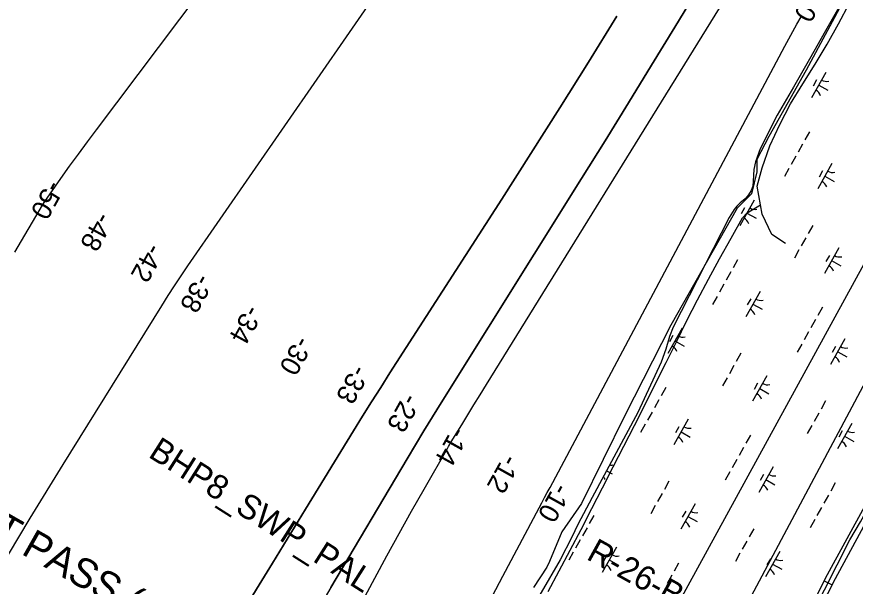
# Model space of a CAD drawing. Extents: x 3913936 to 3933962, y 195330 to 217741.
# Drawn here: x 3927100 to 3928535, y 208120 to 209094 of the extents above; entities that cross this region are included whole.
import ezdxf

# ---------------------------------------------------------------- set-up
doc = ezdxf.new("R2010")
doc.units = 0
for name, color, linetype in [('V-CHAN-NAID', 7, 'Continuous'), ('V-RIVR-EDGE', 7, 'Continuous'), ('V-RIVR-GAGE-IDEN', 7, 'Continuous'), ('V-RIVR-RANG', 7, 'Continuous'), ('V-RIVR-RANG-IDEN', 7, 'Continuous'), ('V-ROAD-CNTR', 7, 'Continuous'), ('V-RRAP-FSHR', 7, 'Continuous'), ('V-TOPO-DPTH', 7, 'Continuous'), ('V-TOPO-MAJR', 7, 'Continuous'), ('V-TOPO-MINR', 7, 'Continuous'), ('V-UTIL-LINE', 7, 'Continuous'), ('V-WETL-SWMP', 7, 'Continuous')]:
    doc.layers.add(name, color=color, linetype=linetype)

msp = doc.modelspace()

# ---------------------------------------------------------------- linework, layer by layer
at = {"layer": 'V-RIVR-EDGE'}
msp.add_lwpolyline([(3928556.5, 209199.4), (3928450.9, 209002.8), (3928386.8, 208889.3), (3928366.6, 208850), (3928366.6, 208828.7), (3928357.6, 208791.6), (3928332.9, 208766.9), (3928219.4, 208566.9), (3928140.8, 208411.9), (3928066.7, 208261.4), (3928033, 208213.1), (3928011.6, 208162.5), (3928007.1, 208152.4), (3927984.7, 208117.6)], dxfattribs=at)
at = {"layer": 'V-ROAD-CNTR'}
msp.add_line((3928482, 208129.1), (3928495.4, 208122.3), dxfattribs=at)
for points in [[(3928044.2, 207343.6), (3928094.5, 207444.5), (3928133.3, 207517.5), (3928180.5, 207605.3), (3928235.4, 207695.3), (3928288.8, 207774.9), (3928328.2, 207845), (3928371.8, 207915), (3928403.4, 207978.7), (3928448.6, 208063), (3928487.6, 208140.1), (3928551.3, 208257.1), (3928589.1, 208328.3), (3928660.5, 208463), (3928682.4, 208493.9)], [(3928387.7, 207913.2), (3928416.7, 207971.8), (3928461.9, 208056.1), (3928500.9, 208133.1), (3928564.5, 208250)], [(3927948.7, 207158.5), (3927983, 207221.8), (3928027.3, 207302.1), (3928070.8, 207383.9), (3928132.7, 207501), (3928178.9, 207584.5), (3928208, 207638.7), (3928249, 207705.3), (3928302.8, 207784.1), (3928343.9, 207858.3), (3928395.8, 207942.8), (3928525.9, 208199.6)]]:
    msp.add_lwpolyline(points, dxfattribs=at)
msp.add_spline([(3928525.9, 208199.6), (3928663.5, 208448.7), (3928729.3, 208575.7), (3928772.5, 208644.8), (3928793, 208671.2), (3928813.2, 208686), (3928850, 208702.1), (3928901.4, 208723.3), (3928941.2, 208746.5), (3928980.6, 208763.6), (3929011.7, 208780.2), (3929053.1, 208788.8), (3929116.6, 208799.7), (3929152.6, 208808.4), (3929198.1, 208822), (3929228.3, 208840.3), (3929280.5, 208872.7), (3929342.1, 208906.6), (3929394.3, 208930.8), (3929439, 208947.7), (3929467.8, 208956.8), (3929496.7, 208976.4), (3929523.6, 209009.7), (3929552.1, 209061.3), (3929562.8, 209097.6), (3929549.9, 209122.5), (3929531.6, 209153.6), (3929490.5, 209225.5), (3929461.6, 209289.1), (3929459.6, 209329.4)], degree=3, dxfattribs=at)
at = {"layer": 'V-RRAP-FSHR'}
for points in [[(3928415.6, 208706.5), (3928392, 208721.8), (3928375.9, 208756.5), (3928367.3, 208804.2), (3928375.7, 208835.6), (3928388.7, 208873.3), (3928405.6, 208909.9), (3928423.9, 208945.1), (3928445.1, 208979.4), (3928466.4, 209012.9), (3928486.9, 209047.2), (3928506.2, 209082.3), (3928525.1, 209117.5)], [(3928009.7, 208111.3), (3928028.5, 208146.6), (3928047.2, 208182), (3928065.9, 208217.3), (3928084.2, 208252.9), (3928102.4, 208288.5), (3928120.6, 208324.1), (3928139, 208359.7), (3928157.3, 208395.2), (3928175.5, 208430.8), (3928193.3, 208466.7), (3928211.6, 208502.5), (3928228.9, 208538.3), (3928246.8, 208574.8), (3928264.8, 208609.8), (3928283.8, 208645.2), (3928302.9, 208680.2), (3928322.6, 208715.3), (3928341.9, 208750), (3928350.1, 208758.8), (3928373, 208772.3)]]:
    msp.add_lwpolyline(points, dxfattribs=at)
at = {"layer": 'V-TOPO-DPTH'}
for points in [[(3927068.2, 208144.7), (3927123.5, 208236.7), (3927179.7, 208328.3), (3927348.6, 208600), (3927359.4, 208617.2), (3927370.5, 208634.2), (3927381.8, 208651.2), (3927393.2, 208668), (3927780.5, 209227.3), (3927802.6, 209259), (3927824.8, 209290.6), (3927847.3, 209322), (3927869.9, 209353.4), (3927910.8, 209409.7), (3927913.1, 209412.8), (3927915.4, 209415.9), (3927917.8, 209419), (3927920.1, 209422.1), (3927962.4, 209477), (3928558.3, 210083.6), (3928575.6, 210105.9), (3928593, 210128), (3928610.7, 210149.9), (3928628.4, 210171.7)], [(3927068.2, 208144.7), (3927123.5, 208236.7), (3927179.7, 208328.3), (3927348.6, 208600), (3927359.4, 208617.2), (3927370.5, 208634.2), (3927381.8, 208651.2), (3927393.2, 208668), (3927780.5, 209227.3), (3927802.6, 209259), (3927824.8, 209290.6), (3927847.3, 209322), (3927869.9, 209353.4), (3927910.8, 209409.7), (3927913.1, 209412.8), (3927915.4, 209415.9), (3927917.8, 209419), (3927920.1, 209422.1), (3927962.4, 209477), (3927986.8, 209501.8)], [(3928264.6, 209139.6), (3928226.2, 209076.5), (3928186.6, 209011.6), (3928146.8, 208946.8), (3928106.8, 208882.2), (3928066.6, 208817.7), (3927826.4, 208433.6), (3927811.7, 208409.7), (3927797, 208385.9), (3927782.5, 208361.9), (3927768.2, 208337.8), (3927637.8, 208117.9), (3927579.5, 208018.9), (3927521.6, 207919.6), (3927464.3, 207820.1), (3927407.3, 207720.3), (3927308, 207545.4), (3927301, 207532.9), (3927294, 207520.4), (3927287, 207507.8), (3927280.1, 207495.3), (3927231.5, 207406.3)], [(3928264.6, 209139.6), (3928226.2, 209076.5), (3928186.6, 209011.6), (3928146.8, 208946.8), (3928106.8, 208882.2), (3928066.6, 208817.7), (3927826.4, 208433.6), (3927811.7, 208409.7), (3927797, 208385.9), (3927782.5, 208361.9), (3927768.2, 208337.8), (3927637.8, 208117.9)], [(3927038.6, 207382.4), (3927156.9, 207550), (3927168.8, 207567.2), (3927180.5, 207584.4), (3927191.8, 207601.9), (3927203, 207619.5), (3927367.6, 207884.4), (3927424.5, 207976.1), (3927481.2, 208067.8), (3927537.8, 208159.7), (3927594.3, 208251.7), (3927676.5, 208385.8), (3927691.9, 208410.7), (3927707.4, 208435.5), (3927723, 208460.2), (3927738.8, 208484.9), (3927930.3, 208782.3), (3927980.1, 208860.2), (3928029.6, 208938.3), (3928078.6, 209016.7), (3928127.2, 209095.3)], [(3928127.2, 209095.3), (3928078.6, 209016.7), (3928029.6, 208938.3), (3927980.1, 208860.2), (3927930.3, 208782.3), (3927738.8, 208484.9), (3927723, 208460.2), (3927707.4, 208435.5), (3927691.9, 208410.7), (3927676.5, 208385.8), (3927594.3, 208251.7), (3927537.8, 208159.7), (3927481.2, 208067.8), (3927424.5, 207976.1), (3927367.6, 207884.4), (3927203, 207619.5), (3927191.8, 207601.9), (3927180.5, 207584.4), (3927168.8, 207567.2), (3927156.9, 207550), (3927038.6, 207382.4)], [(3927231.5, 207406.3), (3927520, 207339.4), (3927529.9, 207360.6), (3927539.9, 207381.8), (3927550.3, 207402.8), (3927560.9, 207423.6), (3927790.8, 207867.9), (3927825.8, 207935.4), (3927861, 208002.8), (3927896.4, 208070.1), (3927932, 208137.3), (3927994, 208254.1), (3927998.7, 208262.8), (3928003.3, 208271.6), (3928008, 208280.4), (3928012.7, 208289.1), (3928414.4, 209043.8), (3928421.2, 209056.5), (3928428.2, 209069.2), (3928435.2, 209081.8), (3928442.3, 209094.4)]]:
    msp.add_lwpolyline(points, dxfattribs=at)
at = {"layer": 'V-TOPO-MAJR'}
msp.add_lwpolyline([(3927097, 208691.7), (3927144.5, 208772.2), (3927145.4, 208773.7), (3927147.3, 208776.6), (3927148.3, 208778.1), (3927175.9, 208817.4), (3927190.9, 208838.4), (3927205.9, 208859.3), (3927221.2, 208880.1), (3927236.6, 208900.7), (3927699.3, 209515.6), (3927711.7, 209532), (3927724.1, 209548.5), (3927736.5, 209564.9), (3927749, 209581.3), (3928265.5, 210260.9)], dxfattribs=at)
at = {"layer": 'V-TOPO-MINR'}
for points in [[(3927068.2, 208144.7), (3927123.5, 208236.7), (3927179.7, 208328.3), (3927348.6, 208600), (3927359.4, 208617.2), (3927370.5, 208634.2), (3927381.8, 208651.2), (3927393.2, 208668), (3927780.5, 209227.3), (3927802.6, 209259), (3927824.8, 209290.6), (3927847.3, 209322), (3927869.9, 209353.4), (3927910.8, 209409.7), (3927913.1, 209412.8), (3927915.4, 209415.9), (3927917.8, 209419), (3927920.1, 209422.1), (3927962.4, 209477), (3928558.3, 210083.6), (3928575.6, 210105.9), (3928593, 210128), (3928610.7, 210149.9), (3928628.4, 210171.7)], [(3927386.2, 207525.1), (3927713, 208134), (3927733.7, 208172.2), (3927754.7, 208210.4), (3927775.9, 208248.3), (3927797.4, 208286.2), (3927837.7, 208356.6), (3927839.2, 208359.2), (3927840.6, 208361.7), (3927842.1, 208364.2), (3927843.7, 208366.8), (3927861.6, 208396.2), (3927872.1, 208413.4), (3927882.6, 208430.6), (3927893.2, 208447.7), (3927903.8, 208464.9), (3928332.2, 209157.2)], [(3927637.8, 208117.9), (3927768.2, 208337.8), (3927782.5, 208361.9), (3927797, 208385.9), (3927811.7, 208409.7), (3927826.4, 208433.6), (3928066.6, 208817.7), (3928106.8, 208882.2), (3928146.8, 208946.8), (3928186.6, 209011.6), (3928226.2, 209076.5), (3928264.6, 209139.6)], [(3927038.6, 207382.4), (3927156.9, 207550), (3927168.8, 207567.2), (3927180.5, 207584.4), (3927191.8, 207601.9), (3927203, 207619.5), (3927367.6, 207884.4), (3927424.5, 207976.1), (3927481.2, 208067.8), (3927537.8, 208159.7), (3927594.3, 208251.7), (3927676.5, 208385.8), (3927691.9, 208410.7), (3927707.4, 208435.5), (3927723, 208460.2), (3927738.8, 208484.9), (3927930.3, 208782.3), (3927980.1, 208860.2), (3928029.6, 208938.3), (3928078.6, 209016.7), (3928127.2, 209095.3)], [(3927520, 207339.4), (3927529.9, 207360.6), (3927539.9, 207381.8), (3927550.3, 207402.8), (3927560.9, 207423.6), (3927790.8, 207867.9), (3927825.8, 207935.4), (3927861, 208002.8), (3927896.4, 208070.1), (3927932, 208137.3), (3927994, 208254.1), (3927998.7, 208262.8), (3928003.3, 208271.6), (3928008, 208280.4), (3928012.7, 208289.1), (3928414.4, 209043.8), (3928421.2, 209056.5), (3928428.2, 209069.2), (3928435.2, 209081.8), (3928442.3, 209094.4)]]:
    msp.add_lwpolyline(points, dxfattribs=at)
at = {"layer": 'V-UTIL-LINE'}
for points in [[(3928017.7, 207698.3), (3929347.6, 210129), (3930421.7, 211210.3)], [(3930525.7, 211151.4), (3928710.9, 208768), (3928100.1, 207621.2)]]:
    msp.add_lwpolyline(points, dxfattribs=at)
at = {"layer": 'V-WETL-SWMP'}
for p, q in [((3928484.7, 208999), (3928460.2, 208955.4)), ((3928468.7, 208986.2), (3928462.8, 208975.8)), ((3928472.5, 208977.2), (3928488.2, 208968.4)), ((3928456.7, 208897.4), (3928448.9, 208883.5)), ((3928444.9, 208876.5), (3928437.1, 208862.6)), ((3928433.2, 208855.6), (3928425.3, 208841.6)), ((3928495.1, 208843.2), (3928470.6, 208799.6)), ((3928421.4, 208834.7), (3928413.6, 208820.7)), ((3928479.1, 208830.5), (3928473.2, 208820)), ((3928482.9, 208821.4), (3928498.6, 208812.6)), ((3928361.7, 208780.3), (3928337.2, 208736.7)), ((3928345.7, 208767.5), (3928339.8, 208757)), ((3928349.5, 208758.5), (3928365.2, 208749.7)), ((3928462.2, 208737.2), (3928454.3, 208723.3)), ((3928450.4, 208716.3), (3928442.6, 208702.4)), ((3928438.6, 208695.4), (3928430.8, 208681.5)), ((3928506.7, 208698.8), (3928482.2, 208655.2)), ((3928490.7, 208686), (3928484.8, 208675.5)), ((3928333.7, 208678.7), (3928325.9, 208664.7)), ((3928494.5, 208677), (3928510.2, 208668.2)), ((3928322, 208657.7), (3928314.1, 208643.8)), ((3928310.2, 208636.8), (3928302.4, 208622.9)), ((3928372.1, 208624.5), (3928347.6, 208580.9)), ((3928298.5, 208615.9), (3928290.6, 208602)), ((3928356.1, 208611.7), (3928350.2, 208601.2)), ((3928359.9, 208602.7), (3928375.6, 208593.9)), ((3928478.7, 208597.2), (3928470.9, 208583.2)), ((3928467, 208576.2), (3928459.1, 208562.3)), ((3928238.8, 208561.5), (3928214.3, 208517.9)), ((3928455.2, 208555.3), (3928447.4, 208541.4)), ((3928222.7, 208548.7), (3928216.9, 208538.3)), ((3928226.5, 208539.7), (3928242.2, 208530.9)), ((3928517.1, 208543), (3928492.6, 208499.4)), ((3928443.5, 208534.4), (3928435.6, 208520.4)), ((3928501.1, 208530.2), (3928495.2, 208519.7)), ((3928339.2, 208518.5), (3928331.4, 208504.5)), ((3928504.9, 208521.2), (3928520.6, 208512.4)), ((3928327.4, 208497.6), (3928319.6, 208483.6)), ((3928383.8, 208480), (3928359.3, 208436.4)), ((3928315.7, 208476.6), (3928307.8, 208462.7)), ((3928367.7, 208467.2), (3928361.9, 208456.8)), ((3928210.8, 208459.9), (3928202.9, 208446)), ((3928371.5, 208458.2), (3928387.2, 208449.4)), ((3928199, 208439), (3928191.2, 208425)), ((3928484.2, 208437), (3928476.4, 208423)), ((3928187.2, 208418.1), (3928179.4, 208404.1)), ((3928472.4, 208416.1), (3928464.6, 208402.1)), ((3928175.5, 208397.1), (3928167.6, 208383.2)), ((3928249.2, 208405.7), (3928224.7, 208362.1)), ((3928460.7, 208395.1), (3928452.8, 208381.2)), ((3928528.8, 208398.5), (3928504.3, 208354.9)), ((3928233.1, 208392.9), (3928227.3, 208382.5)), ((3928236.9, 208383.9), (3928252.6, 208375.1)), ((3928512.7, 208385.7), (3928506.9, 208375.3)), ((3928355.8, 208378.4), (3928347.9, 208364.5)), ((3928516.5, 208376.7), (3928532.2, 208367.9)), ((3928344, 208357.5), (3928336.2, 208343.5)), ((3928332.2, 208336.6), (3928324.4, 208322.6)), ((3928394.2, 208324.2), (3928369.7, 208280.6)), ((3928109.5, 208317.6), (3928119.2, 208312.1)), ((3928320.5, 208315.6), (3928312.6, 208301.7)), ((3928378.1, 208311.4), (3928372.3, 208301)), ((3928216.2, 208299.7), (3928208.4, 208285.8)), ((3928381.9, 208302.4), (3928397.6, 208293.6)), ((3928500.8, 208296.9), (3928492.9, 208282.9)), ((3928204.5, 208278.8), (3928196.6, 208264.9)), ((3928489, 208276), (3928481.2, 208262)), ((3928192.7, 208257.9), (3928184.9, 208243.9)), ((3928260.8, 208261.2), (3928236.3, 208217.7)), ((3928477.2, 208255), (3928469.4, 208241.1)), ((3928087.8, 208241.1), (3928079.9, 208227.2)), ((3928244.8, 208248.5), (3928238.9, 208238)), ((3928248.5, 208239.5), (3928264.2, 208230.6)), ((3928465.5, 208234.1), (3928457.6, 208220.2)), ((3928076, 208220.2), (3928068.2, 208206.3)), ((3928361.2, 208218.2), (3928353.4, 208204.3)), ((3928064.3, 208199.3), (3928056.4, 208185.4)), ((3928349.5, 208197.3), (3928341.6, 208183.4)), ((3928052.5, 208178.4), (3928044.7, 208164.4)), ((3928126.2, 208187), (3928101.7, 208143.4)), ((3928405.8, 208179.7), (3928381.3, 208136.2)), ((3928110.2, 208174.2), (3928104.3, 208163.7)), ((3928113.9, 208165.2), (3928129.6, 208156.3)), ((3928337.7, 208176.4), (3928329.9, 208162.4)), ((3928389.8, 208167), (3928383.9, 208156.5)), ((3928232.8, 208159.6), (3928224.9, 208145.7)), ((3928393.5, 208157.9), (3928409.2, 208149.1)), ((3928221, 208138.7), (3928213.2, 208124.8))]:
    msp.add_line(p, q, dxfattribs=at)
for points in [[(3928511.3, 209118.1), (3928484.2, 209069.9), (3928456.8, 209021.8), (3928429.3, 208973.8), (3928401.5, 208925.9), (3928372.4, 208868.4), (3928364.1, 208845.9), (3928361.4, 208832.8), (3928360, 208812.9), (3928359.6, 208804.4), (3928357.1, 208796.9), (3928352.3, 208789.4), (3928346.4, 208782.9), (3928338.2, 208776.1), (3928332.1, 208770.1), (3928327.5, 208764.4), (3928319.4, 208750.6), (3928223.4, 208563.1), (3928217.4, 208547.3), (3928215.4, 208541.1), (3928213.4, 208533.4), (3928210.9, 208525.4), (3928202.6, 208503.1)], [(3928202.6, 208503.1), (3928162.9, 208417.2), (3928084.9, 208271.8), (3928060.1, 208225.7), (3928050.2, 208203.7), (3928030.2, 208165.4), (3927965.3, 208053.7)]]:
    msp.add_lwpolyline(points, dxfattribs=at)
for centre, start, end in [((3928486.2, 209001.2), 239.8861, 281.4297), ((3928459.1, 208953), 19.8861, 61.4297), ((3928496.6, 208845.4), 239.8861, 281.4297), ((3928469.5, 208797.2), 19.8861, 61.4297), ((3928363.2, 208782.4), 239.8861, 281.4297), ((3928336.2, 208734.3), 19.8861, 61.4297), ((3928508.2, 208700.9), 239.8861, 281.4297), ((3928481.2, 208652.8), 19.8861, 61.4297), ((3928373.6, 208626.6), 239.8861, 281.4297), ((3928346.6, 208578.5), 19.8861, 61.4297), ((3928240.3, 208563.7), 239.8861, 281.4297), ((3928213.2, 208515.5), 19.8861, 61.4297), ((3928518.6, 208545.1), 239.8861, 281.4297), ((3928491.6, 208497), 19.8861, 61.4297), ((3928385.3, 208482.2), 239.8861, 281.4297), ((3928358.2, 208434), 19.8861, 61.4297), ((3928250.7, 208407.9), 239.8861, 281.4297), ((3928530.3, 208400.7), 239.8861, 281.4297), ((3928223.6, 208359.7), 19.8861, 61.4297), ((3928503.2, 208352.5), 19.8861, 61.4297), ((3928117.3, 208344.9), 261.7821, 281.4297), ((3928090.2, 208296.8), 19.8861, 38.0031), ((3928395.7, 208326.4), 239.8861, 281.4297), ((3928368.6, 208278.2), 19.8861, 61.4297), ((3928262.3, 208263.4), 239.8861, 281.4297), ((3928235.2, 208215.3), 19.8861, 61.4297), ((3928127.7, 208189.1), 239.8861, 281.4297), ((3928407.3, 208181.9), 239.8861, 281.4297), ((3928100.6, 208141), 19.8861, 61.4297), ((3928380.2, 208133.7), 19.8861, 61.4297)]:
    msp.add_arc(centre, 17.6, start, end, dxfattribs=at)

# ---------------------------------------------------------------- texts
at = {"layer": 'V-CHAN-NAID'}
msp.add_text('EQUILON SOUTHWEST PASS (-7.5) (2)', height=50, rotation=330.4368, dxfattribs=at).set_placement((3926440.8, 208553.6))
at = {"layer": 'V-RIVR-GAGE-IDEN'}
msp.add_text('BHP8_SWP_PAL', height=41.5, rotation=327.6002, dxfattribs=at).set_placement((3927323.7, 208342.2))
at = {"layer": 'V-RIVR-RANG'}
for s, rotation, p in [('-10', 240.0183, (3928461.4, 209154.5)), ('-50', 241.021, (3927154.3, 208817)), ('-48', 241.021, (3927239.1, 208762.3)), ('-42', 241.021, (3927325.6, 208709.2)), ('-38', 241.021, (3927409.8, 208657.1)), ('-34', 241.021, (3927494.1, 208603.6)), ('-30', 241.021, (3927579.8, 208550.4)), ('-33', 240.8783, (3927676.9, 208501.2)), ('-23', 240.8783, (3927764.2, 208452.5)), ('-14', 240.8783, (3927846.8, 208395.2)), ('-12', 240.8783, (3927935, 208348)), ('-10', 240.8783, (3928022, 208298.7))]:
    msp.add_text(s, height=33.5, rotation=rotation, dxfattribs=at).set_placement(p)
at = {"layer": 'V-RIVR-RANG-IDEN'}
msp.add_text('R-26-B', height=41.5, rotation=331.0211, dxfattribs=at).set_placement((3928073.2, 208167.2))

doc.saveas('drawing.dxf')
